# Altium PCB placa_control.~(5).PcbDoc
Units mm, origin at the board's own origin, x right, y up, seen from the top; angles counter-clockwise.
Board outline 152.4 x 101.6 mm, 2 copper layers (Top Layer, Bottom Layer); 34 components, 26 nets, 130 pads, 0 vias.
Unrouted connection lines stored in the file: 67.
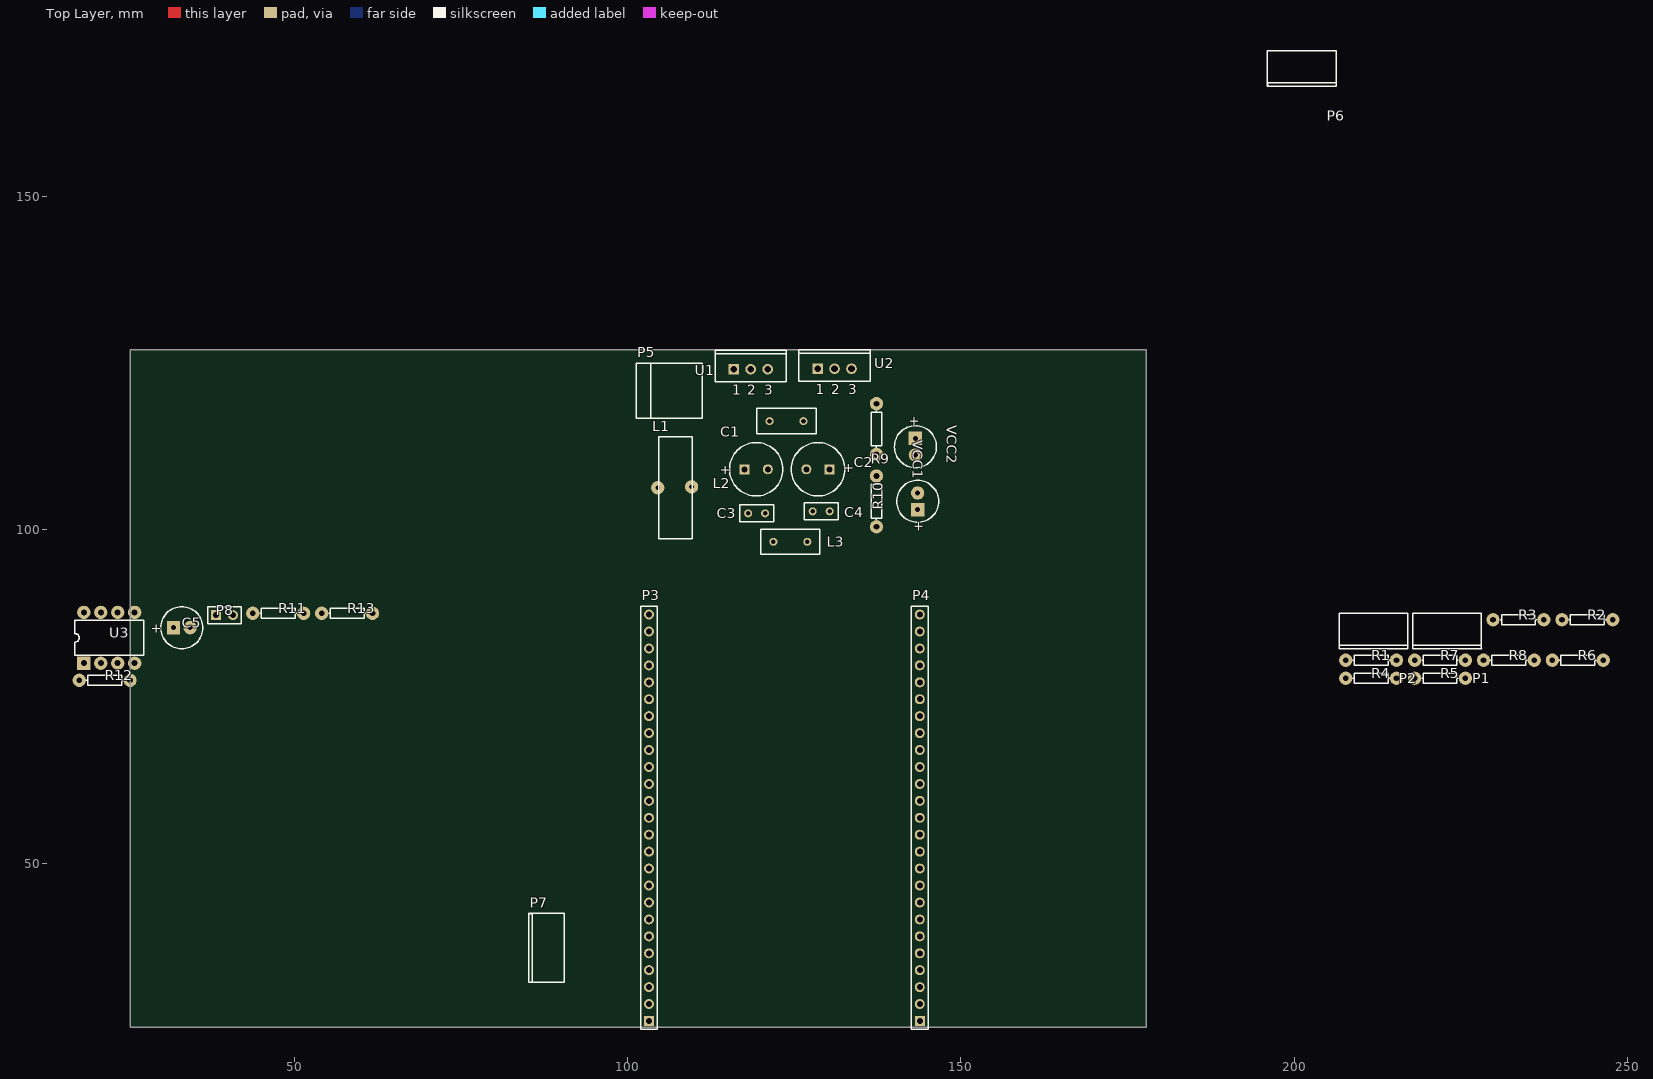
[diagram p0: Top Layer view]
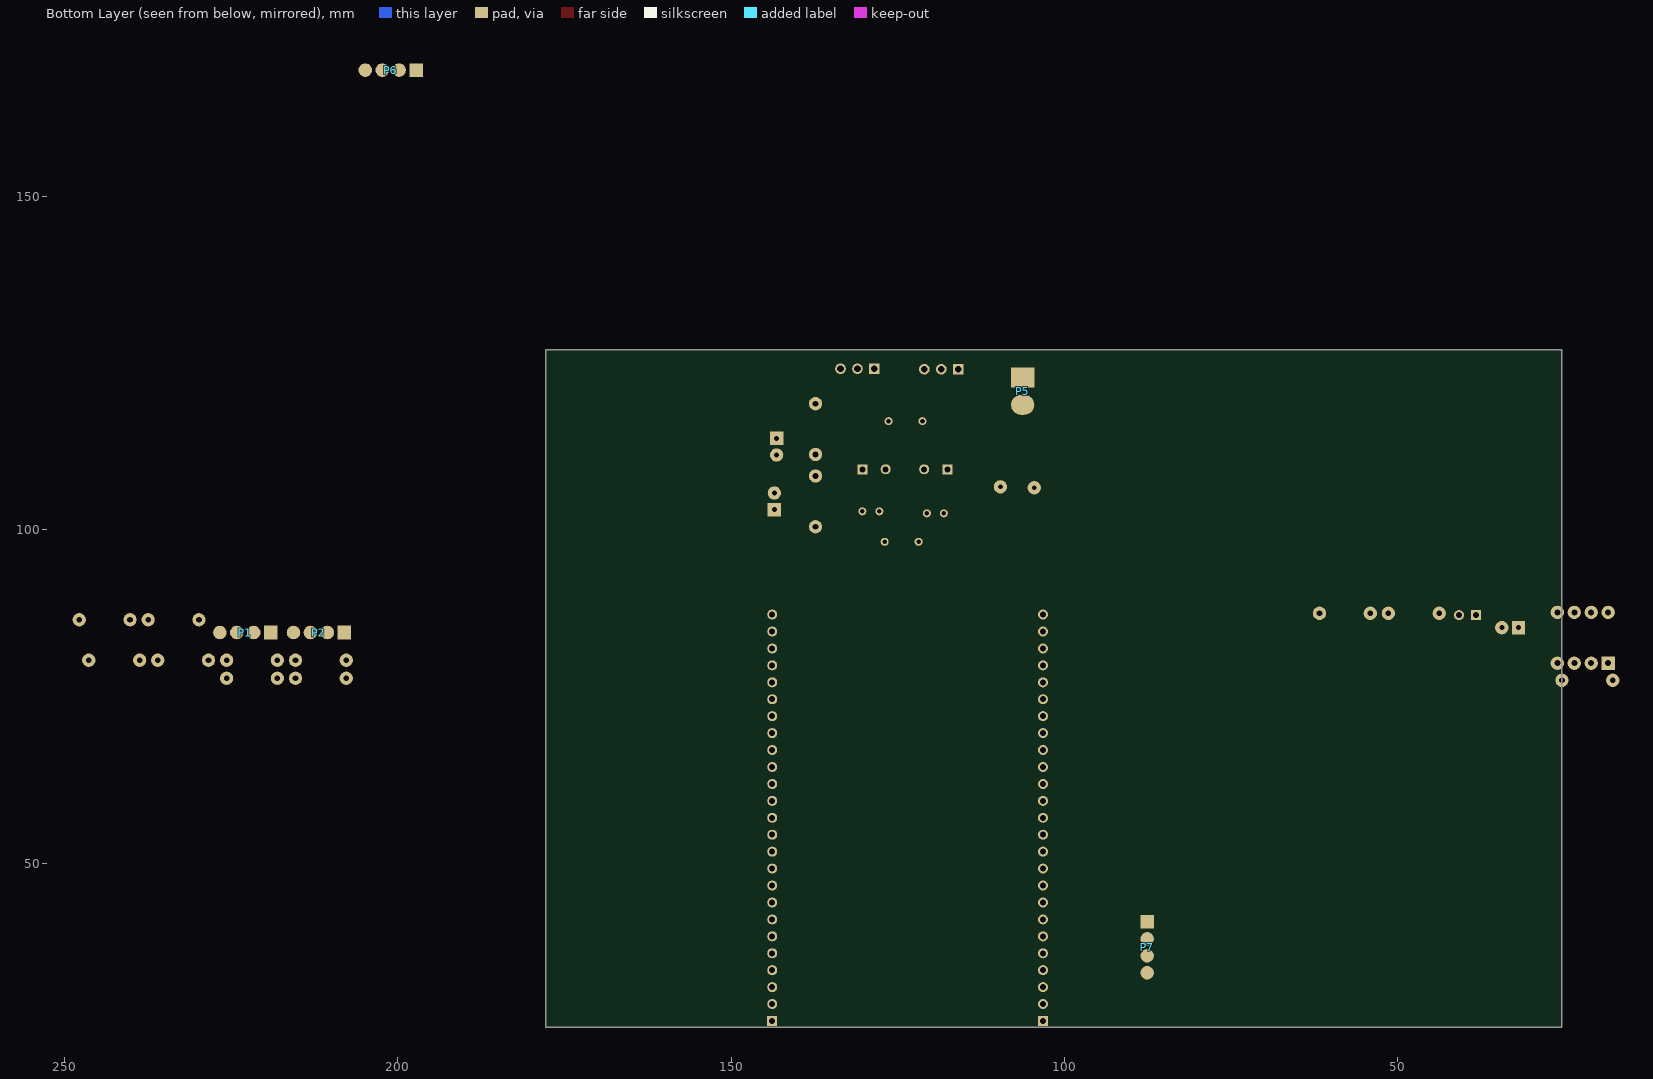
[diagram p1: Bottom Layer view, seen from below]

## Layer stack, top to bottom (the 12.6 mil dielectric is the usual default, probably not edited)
Top Layer: signal copper 0.0356
Dielectric: dielectric 0.32, FR-4, Dk 4.8
Bottom Layer: signal copper 0.0356

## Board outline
25.4,25.4 177.8,25.4 177.8,127 25.4,127

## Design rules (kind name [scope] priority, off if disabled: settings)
Clearance [All] p1: gap=0.254
ComponentClearance [All] p1: gap=0.254 collisioncheckmode=3 verticalgap=0.254
PolygonConnect [All] p1: connectstyle=Relief reliefconductorwidth=0.254 reliefentries=4 polygonreliefangle="90 Angle"
RoomDefinition REGULADOR [InComponentClass('REGULADOR')] p1: confinementstyle=ConfineOut formatcopy=TRUE lockcomponents=FALSE outline 94.85,122.159 93.453,122.159 93.453,110.475 94.85,110.475
RoomDefinition INTERFAZ [InComponentClass('INTERFAZ')] p2: confinementstyle=ConfineIn formatcopy=TRUE lockcomponents=FALSE outline 19.575,27.975 70.375,27.975 70.375,53.375 19.575,53.375
RoomDefinition ENCODER [InComponentClass('ENCODER')] p3: confinementstyle=ConfineIn formatcopy=TRUE lockcomponents=FALSE outline 206.375,62.738 257.175,62.738 257.175,88.138 206.375,88.138
RoomDefinition BOARD-ARM [InComponentClass('BOARD-ARM')] p4: confinementstyle=ConfineOut formatcopy=TRUE lockcomponents=FALSE outline 166.025,120.7 232.827,120.7 232.827,146.1 166.025,146.1
RoomDefinition placa_control_esquema [InComponentClass('placa_control_esquema')] p5: confinementstyle=ConfineIn formatcopy=TRUE lockcomponents=FALSE outline 129.325,143.075 180.125,143.075 180.125,168.475 129.325,168.475
RoutingVias [All] p1: holewidth=0.711 width=1.27 viastyle="Through Hole" minholewidth=0.711 minwidth=1.27 maxholewidth=0.711 maxwidth=1.27
SolderMaskExpansion [All] p1: expansion=0.102
TestPointUsage [All] p1: valid=0 allowmultiple=FALSE
Testpoint [All] p1: side=15 testpointundercomponent=TRUE minsize=1.016 maxsize=2.54 preferedsize=1.524 minholesize=0 maxholesize=1.016 preferedholesize=0.813 testpointgrid=0.025 style=1023 order=0-112345678
Width [All] p1: maxlimit=0.254 minlimit=0.254 preferedwidth=0.254
18 further rules are at their usual default settings.

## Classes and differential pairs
component class INTERFAZ: C5 P8 R11 R12 R13 U3
component class ENCODER: P1 P2 R1 R2 R3 R4 R5 R6 R7 R8
component class BOARD-ARM: P3 P4
component class REGULADOR: C1 C2 C3 C4 L1 L2 L3 P5 R9 R10 U1 U2 VCC1 VCC2
component class placa_control_esquema: P6 P7

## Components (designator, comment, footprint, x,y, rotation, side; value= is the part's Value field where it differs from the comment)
C1 "Cap Pol3" CAPPR3.5-8X15 119.305,109.095 r0 top
C2 "Cap Pol3" CAPPR3.5-8X15 128.576,109.095 r180 top
C3 "Cap" RAD-0.1 119.376,102.486 r180 top
C4 "Cap" RAD-0.1 129.053,102.791 r0 top
C5 "Cap" CAPPR2.5-6.3X5 33.157,85.334 r0 top
L1 "Inductor Iron" bobina_Choque 104.663,108.865 r270 top
L2 "Inductor" RAD-0.2 123.851,116.309 r0 top
L3 "Inductor" RAD-0.2 124.431,98.219 r0 top
P1 "Header 4" HDR1X5 226.695,76.989 r0 top
P2 "Header 4" HDR1X5 215.646,76.989 r0 top
P3 "Header 25" HDR1X25 103.226,26.34 r90 top
P4 "Header 25" HDR1X25 143.84,26.34 r90 top
P5 "Header 2" pwheader1x2 106.286,120.665 r270 top
P6 "Header 4" HDR1X5 204.881,161.349 r0 top
P7 "Header 4" HDR1X5 79.985,33.579 r270 top
P8 "Header 2" HDR1X2 38.285,87.214 r0 top
R1 "metal film 2%" AXIAL-0.3 211.541,80.459 r0 top
R2 "metal film 2%" AXIAL-0.3 243.97,86.528 r0 top
R3 "metal film 2%" AXIAL-0.3 233.639,86.528 r0 top
R4 "metal film 2%" AXIAL-0.3 211.541,77.748 r0 top
R5 "metal film 2%" AXIAL-0.3 221.872,77.748 r0 top
R6 "metal film 2%" AXIAL-0.3 242.534,80.459 r0 top
R7 "metal film 2%" AXIAL-0.3 221.872,80.459 r0 top
R8 "metal film 2%" AXIAL-0.3 232.203,80.459 r0 top
R9 "Carbon 1/8w 5%" AXIAL-0.3 137.346,104.279 r90 top
R10 "Carbon 1/8w 5%" AXIAL-0.3 137.346,115.125 r90 top
R11 "Carbon 1/8w 5%" AXIAL-0.3 47.615,87.482 r0 top
R12 "Carbon 1/8w 5%" AXIAL-0.3 21.586,77.438 r0 top
R13 "Carbon 1/8w 5%" AXIAL-0.3 57.946,87.482 r0 top
U1 "LM78L12ACZ" T03B 118.48,124.099 r0 top
U2 "LM78L05ACZ" T03B 131.062,124.165 r0 top
U3 "SN75176BP" 626-05 22.274,83.816 r0 top
VCC1 "LED2" CAPPR2.5-6.3X5 143.518,104.279 r90 top
VCC2 "LED2" CAPPR2.5-6.3X5 143.188,112.484 r270 top

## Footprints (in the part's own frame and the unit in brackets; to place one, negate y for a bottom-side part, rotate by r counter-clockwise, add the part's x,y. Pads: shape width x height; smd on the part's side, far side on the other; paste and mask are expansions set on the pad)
626-05 [mm] "DIP; 8 Leads; Row Spacing 7.62 mm; Pitch 2.54 mm"
  rect 2x2 hole 0.9: 1(-3.81,-3.81)
  round 2 hole 0.9: 2(-1.27,-3.81) 3(1.27,-3.81) 4(3.81,-3.81) 5(3.81,3.81) 6(1.27,3.81) 7(-1.27,3.81) 8(-3.81,3.81)
  silkscreen extent -5.15,-2.65 5.15,2.65
AXIAL-0.3 [mm] "Resistor; 2 Leads"
  round 2 hole 0.85: 1(-3.81,0) 2(3.81,0)
  silkscreen extent -2.77,-0.76 2.77,0.76
bobina_Choque [mm]
  round 2 hole 0.7: 1(2.54,-0.127) 2(2.413,4.953)
  silkscreen extent -5.08,0 10.16,5.08
CAPPR2.5-6.3X5 [mm] "Capacitor, Electrolytic, Radial; Body 6.3 x 5 mm (Dia.xH typ); Pin Spacing 2.5 mm (typ)"
  rect 2x2 hole 0.75: 1(-1.25,0)
  round 2 hole 0.75: 2(1.25,0)
  silkscreen extent -3.15,-3.15 3.15,3.15
CAPPR3.5-8X15 [mm] "Capacitor, Electrolytic, Radial; Body 8 x 15 mm (Dia.xH typ); Pin Spacing 3.5 mm (typ)"
  rect 1.5x1.5 hole 0.9: 1(-1.75,0)
  round 1.5 hole 0.9: 2(1.75,0)
  silkscreen extent -4,-4 4,4
HDR1X2 [mm] "Connector; Header; 2 Position"
  rect 1.5x1.5 hole 0.9: 1(0,0)
  round 1.5 hole 0.9: 2(2.54,0)
  silkscreen extent -1.27,-1.27 3.81,1.27
HDR1X5 [mil]
  rect 80x80 smd far side: 1(-300,300)
  round 80 smd far side: 2(-200,300) 3(-100,300) 4(0,300)
  silkscreen extent -350,205 55,415
HDR1X25 [mm] "Connector; Header; 25 Position"
  rect 1.5x1.5 hole 0.9: 1(0,0)
  round 1.5 hole 0.9: 2(2.54,0) 3(5.08,0) 4(7.62,0) 5(10.16,0) 6(12.7,0) 7(15.24,0) 8(17.78,0) 9(20.32,0) 10(22.86,0) 11(25.4,0) 12(27.94,0) 13(30.48,0) 14(33.02,0) 15(35.56,0) 16(38.1,0) 17(40.64,0) 18(43.18,0) 19(45.72,0) 20(48.26,0) 21(50.8,0) 22(53.34,0) 23(55.88,0) 24(58.42,0) 25(60.96,0)
  silkscreen extent -1.27,-1.27 62.23,1.27
pwheader1x2 [mm]
  rect 3x3.5 smd far side: 1(-2.159,0)
  oval 3x3.5 smd far side: 2(1.905,0)
  silkscreen extent -4.32,-4.95 3.94,4.95
RAD-0.1 [mm] "Indicating Instrument; 2 Leads"
  round 1.2 hole 0.7: 1(-1.27,0) 2(1.27,0)
  silkscreen extent -2.54,-1.27 2.54,1.27
RAD-0.2 [mm] "Jumper Wire; 2 Leads"
  round 1.2 hole 0.7: 1(-2.54,0) 2(2.54,0)
  silkscreen extent -4.44,-1.91 4.44,1.91
T03B [mm] "TO, Thru-Hole, Vertical, Heatsink Mounted; 3 In-Line Leads; Pitch 2.54 mm"
  rect 1.6x1.6 hole 1: 1(-2.54,0)
  round 1.6 hole 1: 2(0,0) 3(2.54,0)
  silkscreen extent -5.35,-1.85 5.35,2.85

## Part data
C1: "Polarized Capacitor (Surface Mount)"
C2: "Polarized Capacitor 35V"
C3 C4 C5: "Capacitor"
L1: "Magnetic-Core Inductor"
P1 P2 P6 P7: "Header, 4-Pin"
P3 P4: "Header, 25-Pin"
P5 P8: "Header, 2-Pin"
R1 R2 R3 R4 R5 R6 R7 R8 R9 R10 R11 R12 R13: library part "Res Semi", "Semiconductor Resistor"
U1 U2: "3-Terminal Positive Regulator"
U3: "Differential Bus Transceiver"
VCC1 VCC2: "Typical RED, GREEN, YELLOW, AMBER GaAs LED"

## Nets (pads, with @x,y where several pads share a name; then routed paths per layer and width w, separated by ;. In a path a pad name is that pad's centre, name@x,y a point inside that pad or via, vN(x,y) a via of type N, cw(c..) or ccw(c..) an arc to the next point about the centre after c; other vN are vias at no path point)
+5V: C5.2 P4.2 R10.2 R11.2 U2.3 U3.8
+12V: P1.1 P2.1 P6.4 P7.4 R9.2 U1.3 U2.1
GND: C2.2 C4.1 C5.1 L3.2 P1.2 P2.2 P4.1 P6.3 P7.3 R2.1 R4.1 R6.1 R8.1 R13.1 U1.2 U2.2 U3.5 VCC1.2 VCC2.2
IN_SD_1: P4.21 P6.2
IN_SD_2: P3.19 P7.2
NetC1_1: C1.1 C3.2 L1.2 L2.1
NetC1_2: C1.2 C3.1 L3.1 P5.1
NetC2_1: C2.1 C4.2 L2.2 U1.1
NetL1_1: L1.1 P5.2
NetP1_3: P1.3 R1.2
NetP1_4: P1.4 R3.2
NetP2_3: P2.3 R5.2
NetP2_4: P2.4 R7.2
NetP3_6: P3.6 U3.2 U3.3
NetP3_7: P3.7 U3.1
NetP3_8: P3.8 U3.4
NetP3_20: P3.20 R7.1 R8.2
NetP3_21: P3.21 R5.1 R6.2
NetP4_14: P4.14 R3.1 R4.2
NetP4_15: P4.15 R1.1 R2.2
NetP8_1: P8.1 R11.1 R12.2 U3.6
NetP8_2: P8.2 R12.1 R13.2 U3.7
NetR9_1: R9.1 VCC1.1
NetR10_1: R10.1 VCC2.1
PWM_1: P4.16 P6.1
PWM_2: P3.9 P7.1
pads on no net: P3.1 P3.2 P3.3 P3.4 P3.5 P3.10 P3.11 P3.12 P3.13 P3.14 P3.15 P3.16 P3.17 P3.18 P3.22 P3.23 P3.24 P3.25 P4.3 P4.4 P4.5 P4.6 P4.7 P4.8 P4.9 P4.10 P4.11 P4.12 P4.13 P4.17 P4.18 P4.19 P4.20 P4.22 P4.23 P4.24 P4.25

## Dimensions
159.406,38.95 to 118.806,37.725 on Top Layer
